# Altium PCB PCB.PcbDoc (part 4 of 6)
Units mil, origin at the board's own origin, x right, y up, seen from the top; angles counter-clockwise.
Board outline 7100 x 7000 mil, 4 copper layers (Top Layer, GND, VCC, Bottom Layer), stack 61.2 mil thick; 759 components, 507 nets, 2200 pads, 452 vias.
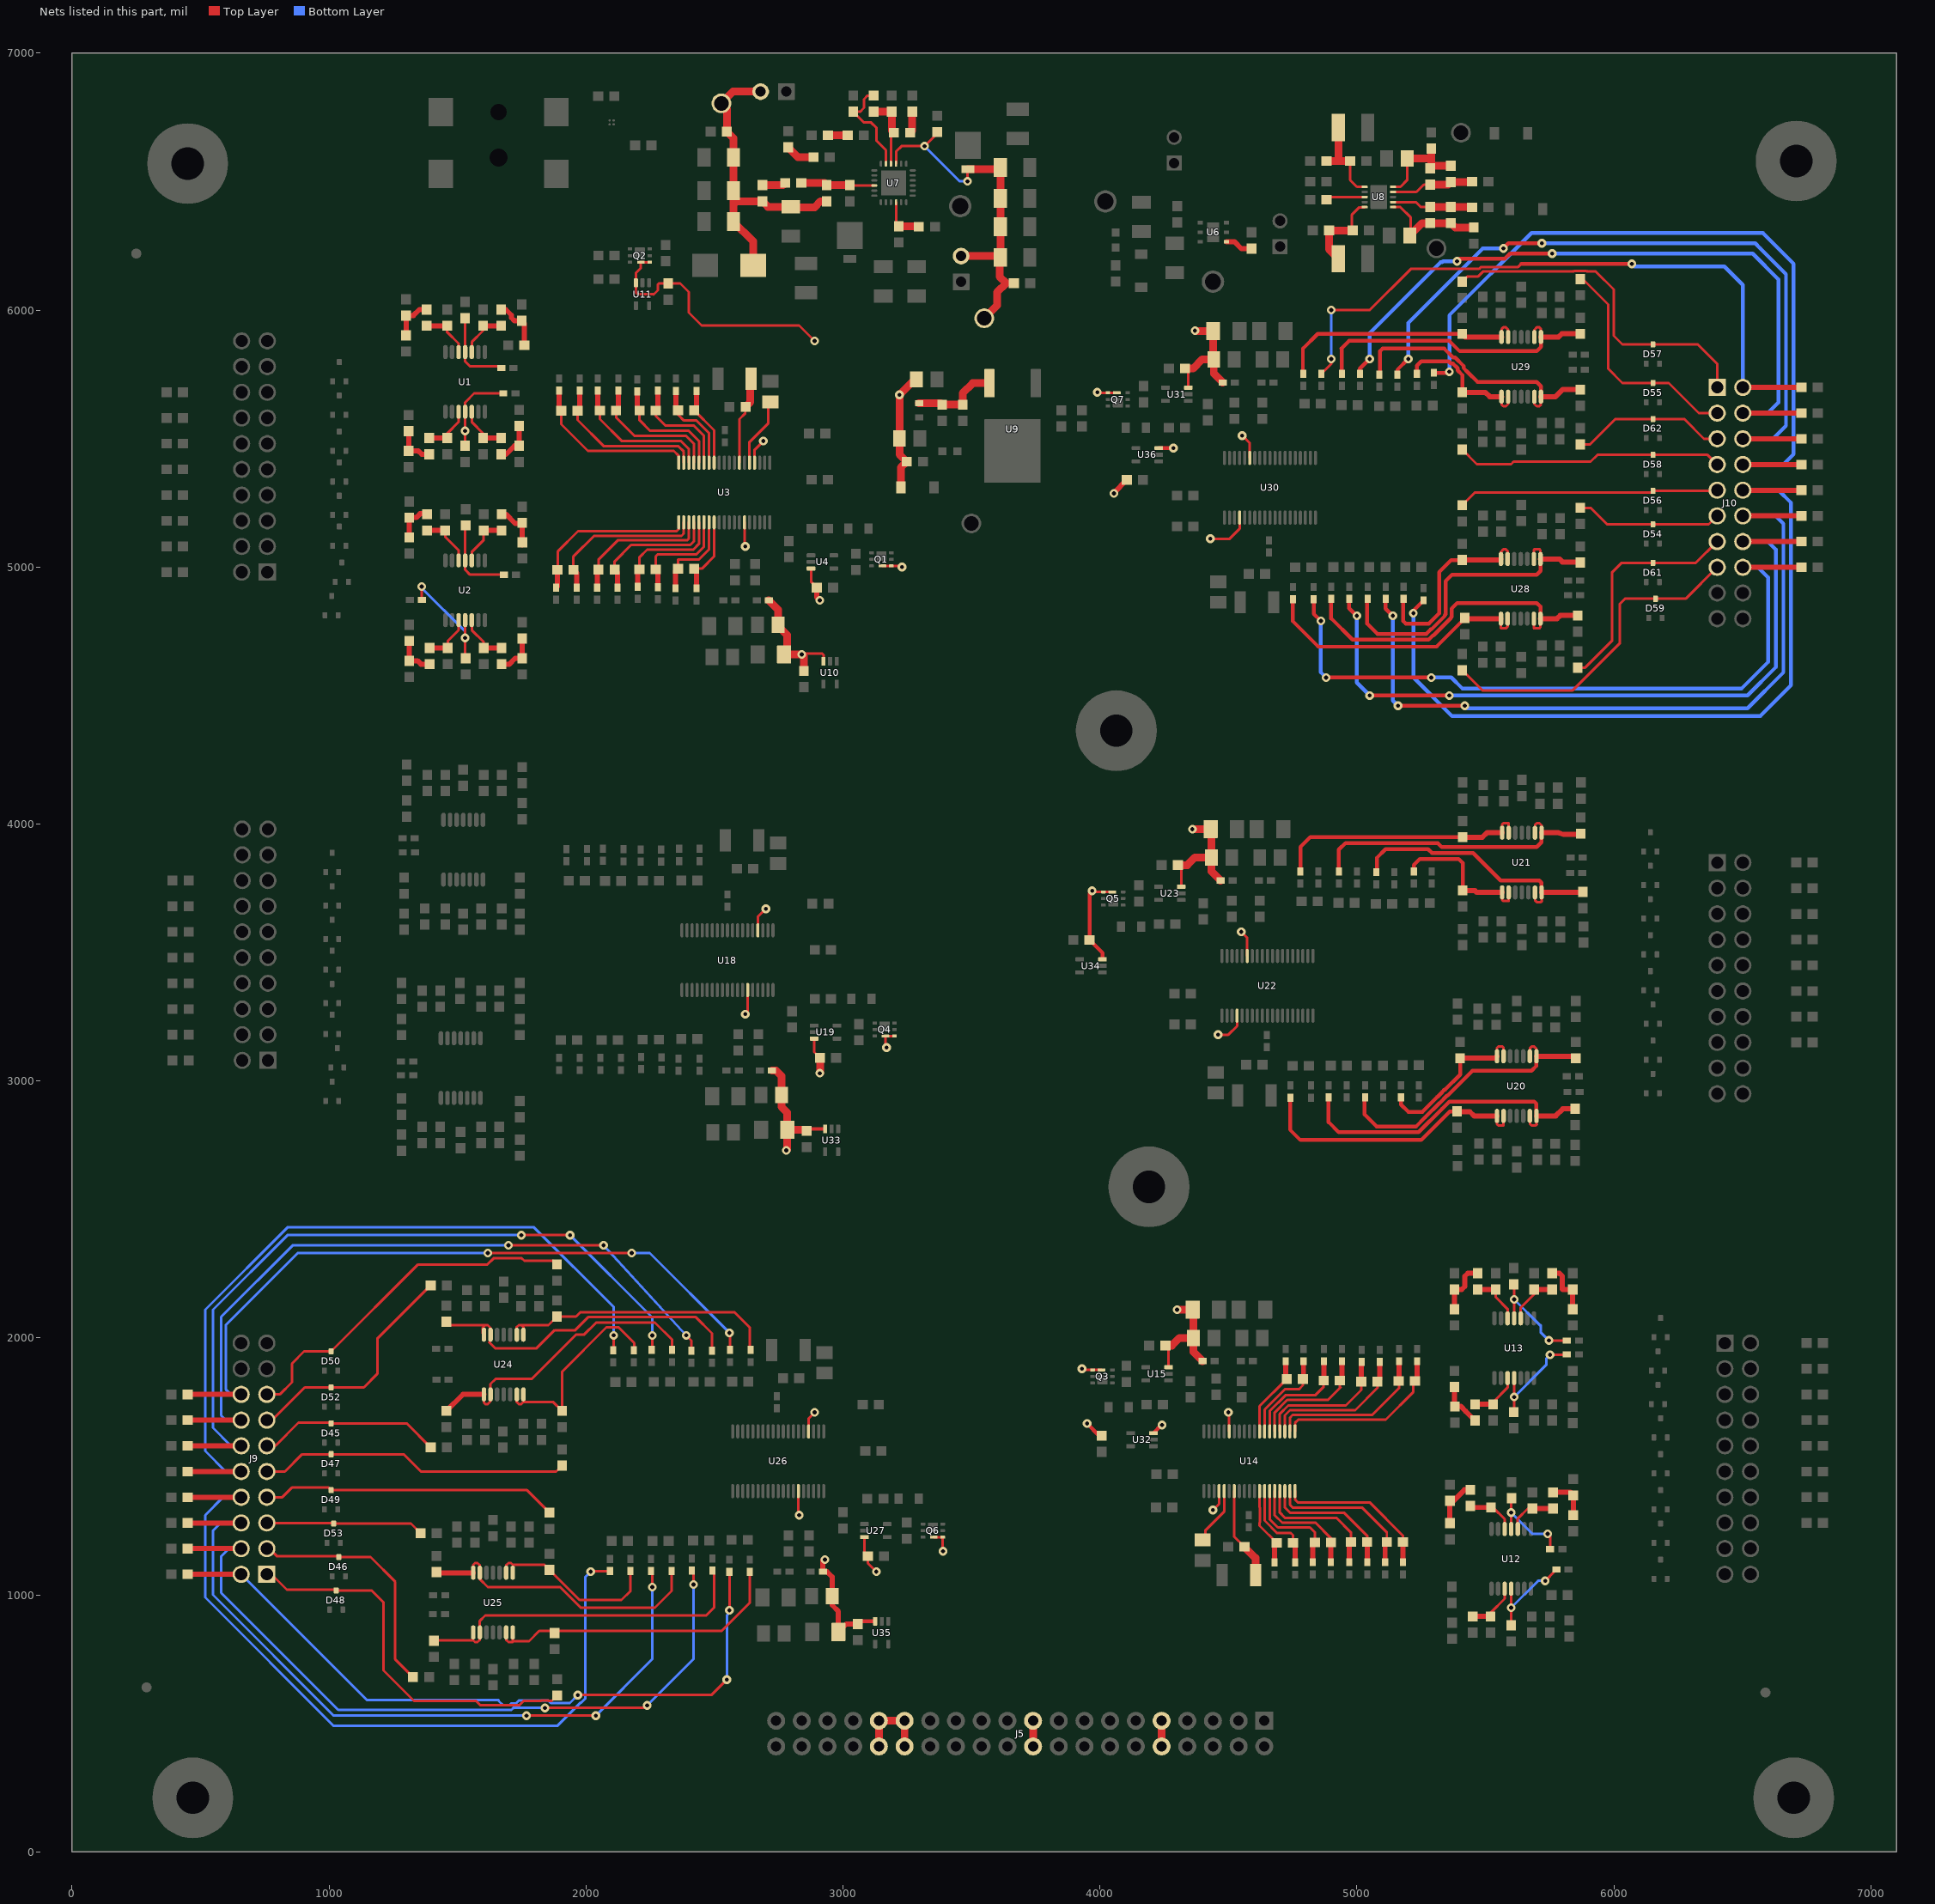
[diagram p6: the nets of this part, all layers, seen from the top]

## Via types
v1: diameter 34, hole 16, Top Layer to Bottom Layer, 440 vias
v2: diameter 19.68, hole 7.87, Top Layer to Bottom Layer, 11 vias
v3: diameter 30, hole 14, Top Layer to Bottom Layer, 1 vias

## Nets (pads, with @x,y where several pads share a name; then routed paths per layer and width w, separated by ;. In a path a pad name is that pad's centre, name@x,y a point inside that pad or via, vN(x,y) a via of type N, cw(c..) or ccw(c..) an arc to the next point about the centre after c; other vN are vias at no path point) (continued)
DGND: C8.2 C9.2 C10.2 C34.2 C70.2 C71.2 C75.2 C83.2 C84.2 C85.2 C109.2 C121.2 C122.2 C123.2 C147.2 C159.2 C160.2 C161.2 C185.2 C197.2 C198.2 C199.2 C223.2 C235.2 C236.2 C237.2 C261.2 C266.2 C267.2 C268.2 C269.2 C270.2 C271.2 D16.2 J5.9 J5.10 J5.19 J5.20 J5.29 J5.30 J5.31 J5.32 Q1.4 Q1.7 Q2.4 Q2.7 Q3.4 Q3.7 Q4.4 Q4.7 Q5.4 Q5.7 Q6.4 Q6.7 Q7.4 Q7.7 R70.2 U3.4 U3.33 U4.3 U10.3 U11.3 U14.4 U14.33 U15.3 U18.4 U18.33 U19.3 U22.4 U22.33 U23.3 U26.4 U26.33 U27.3 U30.4 U30.33 U31.3 U32.3 U33.3 U34.3 U35.3 U36.3 | length 7678
  Top Layer w10: Q2.4@2248.39,6186.38 Q2.7@2213.74,6186.38 2213.74,6164.06 2194.41,6144.72 U11.3@2194.41,6106.26 2194.41,6067.87 2200.32,6061.97 2261.65,6061.97 2263.31,6060.31 2280,6077.01 2280,6100.31 2283.15,6103.46 C75.2@2320,6103.46 2366.54,6103.46 2400,6070 2400,5990 2450,5940 2830,5940 v1(2890,5880) ; U3.33@2617,5173.86 2617,5083 2618.81,5081.19 2618.81,5075.91 v1@2620,5074.72 ; v1(2620,3260) 2629.36,3269.36 U18.33@2629.36,3353.8 ; v1(2620,5080) v1@2620,5074.72 ; v1@2624.04,5070.68 v1@2620,5074.72 ; U3.4@2656.37,5406.14 2656.37,5456.37 v1(2690,5490) ; U18.4@2668.73,3586.09 2668.73,3638.73 v1(2700,3670) ; U26.33@2827,1403.81 2827,1313 v1(2830,1310) ; v1(2840,4660) 2843,4663 2920,4663 2924.41,4658.59 U10.3@2924.41,4633.29 ; U26.4@2866.37,1636.09 2866.37,1686.37 v1(2890,1710) ; U4.3@2875.71,4994.41 2875.71,4942.79 C34.2@2898.5,4920 ; U19.3@2888.07,3164.41 2888.07,3112.8 C147.2@2910.87,3090 ; U27.3@3083.96,1224.41 3083.96,1162.8 C223.2@3096.76,1150 3096.76,1123.24 v1(3130,1090) ; Q1.7@3153.74,5004.41 Q1.4@3188.39,5004.41 3225.59,5004.41 v1(3230,5000) ; v1(3170,3130) 3166.1,3133.9 Q4.7@3166.1,3174.41 Q4.4@3200.75,3174.41 ; Q6.7@3353.74,1224.41 Q6.4@3388.39,1224.41 3388.39,1181.61 3390,1180 v1(3390,1170) ; v1(3930,1880) 3934.41,1875.59 Q3.4@3971.61,1875.59 Q3.7@4006.26,1875.59 ; v1(3970,3740) 3980,3740 3984.41,3735.59 Q5.4@4013.66,3735.59 Q5.7@4048.3,3735.59 ; v1(3990,5680) 4000,5680 4001.98,5678.02 Q7.4@4031.61,5678.02 Q7.7@4066.25,5678.02 ; C109.2@4254.84,1970 4267.64,1957.2 U15.3@4267.64,1885.59 ; C185.2@4303.54,3840 4316.34,3827.21 U23.3@4316.34,3755.59 ; C261.2@4331.5,5772.44 4344.29,5759.65 U31.3@4344.29,5698.03 ; v1(4430,5110) 4505.28,5110 4541.97,5146.69 4541.97,5147.25 4543.78,5149.06 U30.4@4543.78,5192.44 ; v1(4440,1330) 4463.94,1353.94 U14.4@4463.94,1403.86 ; v1(4460,3180) 4500,3180 4533.94,3213.94 U22.4@4533.94,3254.17 ; v1(4500,1710) 4503.31,1706.69 U14.33@4503.31,1636.14 ; v1(4550,3580) 4573.31,3556.69 U22.33@4573.31,3486.46 ; v1(4553.31,5511.18) 4555.12,5511.18 4583.15,5483.15 U30.33@4583.15,5424.72
  Top Layer w15: C268.2@2859,2805.5 2866.8,2813.29 U33.3@2930.41,2813.29 ; C270.2@3058,886.5 3068.8,897.29 U35.3@3125.41,897.29 ; v1(3950,1667) 3997.5,1619.5 C267.2@4007,1619.5 ; v1(3970,3740) 3959.5,3729.5 C269.2@3959.5,3549 4010.29,3498.2 U34.3@4010.29,3473.59 ; U32.3@4208.29,1629.59 4239.7,1661 v1(4242,1661) ; U36.3@4229.29,5462.59 4285.59,5462.59 v1(4286,5463)
  Top Layer w20: C34.2@2898.5,4920 2898.5,4881.5 v1(2910,4870) ; v1(2930,1137) 2924,1137 2921.88,1134.88 C199.2@2921.88,1089.95 2938.26,1089.95 2958.26,1069.95 C197.2@2958.26,995.38 2958.26,959.95 2982.51,935.7 C198.2@2982.51,855.38 3013.62,886.5 C270.2@3058,886.5 ; v1(4055,5287) 4055,5289.5 C271.2@4104.5,5339
  Top Layer w30: C10.2@2711.88,4870 2748.26,4833.62 C8.2@2748.26,4775.38 2748.26,4769.38 2782.26,4735.38 2782.26,4671.08 C9.2@2771.18,4660 v1(2840,4660) 2848,4652 C266.2@2848,4595.5 ; C123.2@2724.24,3040 2740,3040 2760.62,3019.38 C121.2@2760.62,2945.38 2760.62,2899.38 2783.54,2876.46 C122.2@2783.54,2810 ; v1(2780,2730) 2783.54,2733.54 C122.2@2783.54,2810 ; C268.2@2859,2805.5 2854.5,2810 C122.2@2783.54,2810 ; v1(2910,3030) 2910.87,3030.87 C147.2@2910.87,3090 ; J5.32@3140,410 J5.31@3140,510 J5.29@3240,510 J5.30@3240,410 ; D16.2@3225.53,5310 3225.53,5387.03 C71.2@3248.5,5410 3220,5438.5 C70.2@3220,5500 v1(3220,5670) 3280.39,5730.39 R70.2@3286.18,5730.39 ; J5.20@3740,410 J5.19@3740,510 ; J5.10@4240,410 J5.9@4240,510 ; C109.2@4254.84,1970 4280,1970 4310,2000 C83.2@4363.35,2000 ; C185.2@4303.54,3840 4340,3840 4370,3870 C159.2@4433.35,3870 ; v1@4310,2110 C84.2@4360.87,2110 4363.35,2107.52 C83.2@4363.35,2000 ; C261.2@4331.5,5772.44 4362.44,5772.44 4398.26,5808.26 C235.2@4443.19,5808.26 ; v1(4360,3980) C160.2@4430.87,3980 4433.35,3977.52 C159.2@4433.35,3870 ; v1(4370,5920) 4371.74,5918.26 C236.2@4440.71,5918.26 4440.71,5810.74 C235.2@4443.19,5808.26 ; C85.2@4399.72,1910 4363.35,1946.38 C83.2@4363.35,2000 ; C161.2@4469.72,3780 4433.35,3816.38 C159.2@4433.35,3870 ; C237.2@4478.27,5718.26 4443.19,5753.34 C235.2@4443.19,5808.26
  other v1: 4300,2110
DO0+: C164.1 R175.1 U20.8 U20.9 | length 1137.8
  Top Layer w10: U20.9@5673.23,3096.14 5673.23,3126.77 5680,3133.54 5690,3133.54 5698.82,3124.72 U20.8@5698.82,3096.14
  Top Layer w15: R175.1@5031.81,2936.38 5030,2934.57 5030,2870 5076.7,2823.3 5230.95,2823.3 5264.78,2857.13 5322.4,2914.75 5322.88,2914.75 5351.01,2942.87 5352.87,2942.87 5450,3040 5680,3040 5698.82,3058.82 U20.8@5698.82,3096.14
  Top Layer w20: U20.8@5698.82,3096.14 5844.41,3096.14 C164.1@5852.05,3088.5
DO1+: C173.1 R177.1 U20.13 U20.14 | length 635.7
  Top Layer w10: U20.14@5545.28,3096.14 5545.28,3128.82 5550,3133.54 5566.46,3133.54 5570.87,3129.13 U20.13@5570.87,3096.14
  Top Layer w15: R177.1@5171.81,2936.38 5171.81,2908.19 5200,2880 5255.3,2880 5312.93,2937.63 5313.41,2937.63 5332.37,2956.59 5332.37,2957.07 5341.05,2965.75 5343.4,2965.75 5402.05,3024.4 C173.1@5402.05,3088.5
  Top Layer w20: C173.1@5402.05,3088.5 5537.64,3088.5 U20.14@5545.28,3096.14
DO2+: C183.1 R184.1 U21.1 U21.2 | length 584.9
  Top Layer w10: U21.1@5565.28,3733.86 5565.28,3704.72 5570,3700 5590,3700 5590.87,3700.87 U21.2@5590.87,3733.86
  Top Layer w15: R184.1@5221.95,3815.43 5221.95,3841.02 5245.18,3864.25 5395.75,3864.25 5412.05,3847.95 C183.1@5412.05,3741.5
  Top Layer w20: C183.1@5412.05,3741.5 5413.54,3740 5460,3740 5466.14,3733.86 U21.1@5565.28,3733.86
DO3+: C189.1 R187.1 U21.6 U21.7 | length 1062.3
  Top Layer w10: U21.6@5693.23,3733.86 5693.23,3703.23 5700,3696.46 5716.46,3696.46 5720,3700 5718.82,3701.18 U21.7@5718.82,3733.86
  Top Layer w15: R187.1@5076,3812.63 5077.64,3814.27 5077.64,3867.89 5112.13,3902.37 5277.63,3902.37 5292.87,3887.13 5452.87,3887.13 5560,3780 5710,3780 5718.82,3771.18 U21.7@5718.82,3733.86
  Top Layer w20: U21.7@5718.82,3733.86 C189.1@5882.05,3733.86
DO4+: C165.1 R189.1 U21.8 U21.9 | length 1184.2
  Top Layer w10: U21.9@5693.23,3966.14 5693.23,3996.77 5700,4003.54 5710,4003.54 5718.82,3994.72 U21.8@5718.82,3966.14
  Top Layer w15: R189.1@4930,3815.43 4930,3900 4955.63,3925.63 5071.77,3925.63 5072.16,3925.25 5314.75,3925.25 5330,3910 5700,3910 5718.82,3928.82 U21.8@5718.82,3966.14
  Top Layer w20: U21.8@5718.82,3966.14 5783.86,3966.14 5804.45,3959 C165.1@5875,3959
DO5+: C174.1 R191.1 U21.13 U21.14 | length 1000.2
  Top Layer w10: U21.14@5565.28,3966.14 5565.28,3998.82 5570,4003.54 5590,4003.54 5590.87,4002.68 U21.13@5590.87,3966.14
  Top Layer w15: R191.1@4780,3815.43 4780,3910 4818.5,3948.5 C174.1@5412.05,3948.5
  Top Layer w20: C174.1@5412.05,3948.5 5488.5,3948.5 5506.14,3966.14 U21.14@5565.28,3966.14
DO6+: C184.1 R193.1 U20.1 U20.2 | length 1098.3
  Top Layer w10: U20.1@5545.28,2863.86 5545.28,2831.18 5550,2826.46 5570,2826.46 5570.87,2827.32 U20.2@5570.87,2863.86
  Top Layer w15: R193.1@4741.81,2935.08 4740,2933.27 4740,2810 4780,2770 5250,2770 5361.5,2881.5 C184.1@5390,2881.5
  Top Layer w20: C184.1@5390,2881.5 5391.5,2880 5440,2880 5456.14,2863.86 U20.1@5545.28,2863.86
DO7+: C188.1 R195.1 U20.6 U20.7 | length 1281.1
  Top Layer w10: U20.6@5673.23,2863.86 5673.23,2833.23 5680,2826.46 5696.46,2826.46 5700,2830 5698.82,2831.18 U20.7@5698.82,2863.86
  Top Layer w15: R195.1@4890.02,2936.38 4890,2840 4930,2800 5240,2800 5240.43,2800.43 5331.88,2891.88 5332.36,2891.88 5360.48,2920 5362.35,2920 5690,2920 5698.82,2911.18 U20.7@5698.82,2863.86
  Top Layer w20: U20.7@5698.82,2863.86 5773.86,2863.86 5801.5,2891.5 C188.1@5850,2891.5
E0+: D45.3 J9.11 R208.1 | length 714.1
  Top Layer w10: J9.11@758.26,1579.95 791.48,1579.95 881.48,1669.95 1005.66,1669.95 D45.3@1008.26,1667.35 1302.51,1667.35 R208.1@1395.46,1574.4
E0-: J9.12 R219.2 R221.1 | length 2898.1
  Top Layer w10: v1(1748.26,2399.95) v1(1938.26,2399.95) ; R221.1@2255.76,1953.06 2258.26,1955.56 v1(2258.26,2009.95)
  Top Layer w20: R219.2@449.75,1579.95 J9.12@658.26,1579.95
  Bottom Layer w10: J9.12@658.26,1579.95 618.26,1579.95 548.26,1649.95 548.26,2109.95 838.26,2399.95 v1(1748.26,2399.95) ; v1(1938.26,2399.95) 2258.26,2079.95 v1(2258.26,2009.95)
E1+: D47.3 J9.9 R225.1 | length 1213.9
  Top Layer w10: J9.9@758.26,1479.95 828.26,1479.95 895.66,1547.36 D47.3@1008.25,1547.36 1290.85,1547.36 1358.08,1480.13 1884.18,1480.13 R225.1@1906.96,1502.9
E1-: J9.10 R218.2 R224.1 | length 2951.9
  Top Layer w10: R224.1@2105.78,1951.74 2108.26,1954.22 v1(2108.26,2010)
  Top Layer w20: R218.2@449.75,1479.95 J9.10@658.26,1479.95
  Bottom Layer w10: J9.10@658.26,1479.95 598.26,1479.95 518.26,1559.95 518.26,2109.95 838.31,2430 1798.21,2430 2108.26,2119.95 v1(2108.26,2010)
E2+: D49.3 J9.7 R242.1 | length 1155.9
  Top Layer w10: J9.7@758.26,1379.95 818.26,1379.95 855.66,1417.35 998.26,1417.35 D49.3@1008.25,1407.36 1770.69,1407.36 R242.1@1858.26,1319.79
E2-: J9.8 R217.2 R231.1 | length 3006
  Top Layer w10: v1(2018.26,1089.95) 2020.65,1092.34 R231.1@2093.5,1092.34
  Top Layer w20: R217.2@449.75,1379.95 J9.8@658.26,1379.95
  Bottom Layer w10: J9.8@658.26,1379.95 588.26,1379.95 518.26,1309.95 518.26,989.95 1018.26,489.95 1888.26,489.95 1978.38,580.08 1980.63,580.08 1998.13,597.58 1998.13,599.82 1998.26,599.95 1998.26,1069.95 v1(2018.26,1089.95)
E3+: D53.3 J9.5 R251.1 | length 625.5
  Top Layer w10: J9.5@765.66,1287.35 J9.5@758.26,1279.95 1015.66,1279.95 D53.3@1018.25,1277.36 1319.35,1277.36 R251.1@1356.76,1239.95
E3-: J9.6 R216.2 R233.1 | length 2921.1
  Top Layer w10: v1(1768.26,529.95) v1(2038.26,529.95) ; R233.1@2253.52,1092.34 2258.26,1087.61 v1(2258.26,1029.95)
  Top Layer w20: R216.2@449.75,1279.95 J9.6@658.26,1279.95
  Bottom Layer w10: J9.6@658.26,1279.95 578.26,1279.95 548.26,1249.95 548.26,999.95 1018.26,529.95 v1(1768.26,529.95) ; v1(2038.26,529.95) 2258.26,749.95 v1(2258.26,1029.95)
E4+: D46.3 J9.3 R210.1 | length 952.7
  Top Layer w10: J9.3@758.26,1179.95 768.26,1179.95 798.26,1149.95 1035.66,1149.95 D46.3@1038.25,1147.36 1161.64,1147.36 1258,1051 1258,748.71 R210.1@1326.76,679.95
E4-: J9.4 R215.2 R235.1 | length 2902.1
  Top Layer w10: v1(1840,559.95) 2238.26,559.95 v1(2238.26,569.95) ; R235.1@2411.73,1093.98 2418.26,1087.45 v1(2418.26,1039.95)
  Top Layer w20: R215.2@449.75,1179.95 J9.4@658.26,1179.95
  Bottom Layer w10: J9.4@658.26,1179.95 610.3,1179.95 580.3,1149.95 580.3,1007.9 1035.95,552.25 1709.78,552.25 1717.48,559.95 v1(1840,559.95) ; v1(2238.26,569.95) 2418.26,749.95 v1(2418.26,1039.95)
E5+: D48.3 J9.1 R227.1 | length 1514
  Top Layer w10: J9.1@758.26,1079.95 776.21,1079.95 836.21,1019.95 1025.66,1019.95 D48.3@1028.25,1017.36 1165.64,1017.36 1212,971 1212,706.21 1330.58,587.63 1572.37,587.63 1589.87,570.13 1740.13,570.13 1757.63,587.63 1825.43,587.63 1827.63,589.82 1852.37,589.82 1854.57,587.63 1867.43,587.63 R227.1@1888.26,608.45
E5-: J9.2 R214.2 R237.1 | length 2800.4
  Top Layer w10: v1(1968.26,609.95) 2488.26,609.95 v1(2548.26,669.95) ; v1(2558.26,939.95) R237.1@2558.26,1089.95
  Top Layer w20: R214.2@449.75,1079.95 J9.2@658.26,1079.95
  Bottom Layer w10: J9.2@658.26,1079.95 1148.21,590 1660.13,590 1660.13,587.63 1677.63,570.13 1702.37,570.13 1710.07,577.82 1728.88,577.82 1728.88,578.88 1739.82,589.82 1852.37,589.82 1863.32,578.88 1937.18,578.88 v1(1968.26,609.95) ; v1(2548.26,669.95) 2548.26,919.95 2568.26,939.95 v1(2558.26,939.95)
E6+: D50.3 J9.15 R244.1 | length 1400.5
  Top Layer w10: J9.15@758.26,1779.95 808.26,1779.95 855.89,1827.59 855.89,1899.95 903.3,1947.36 D50.3@1008.25,1947.36 1346.79,2285.9 1616.45,2285.9 1640.43,2309.87 1750.13,2309.87 1760.13,2299.87 1872.98,2299.87 R244.1@1886.96,2285.9
E6-: J9.16 R213.2 R239.1 | length 2798.9
  Top Layer w10: v1(1618.26,2329.95) v1(2178.26,2329.95) ; v1(2558.26,2019.95) 2560.21,2018 R239.1@2560.21,1953.06
  Top Layer w20: R213.2@449.75,1779.95 J9.16@658.26,1779.95
  Bottom Layer w10: J9.16@658.26,1779.95 618.26,1779.95 598.26,1799.95 598.26,2049.95 878.26,2329.95 v1(1618.26,2329.95) ; v1(2178.26,2329.95) 2248.26,2329.95 v1(2558.26,2019.95)
E7+: D52.3 J9.13 R247.1 | length 934.8
  Top Layer w10: J9.13@758.26,1679.95 778.26,1679.95 905.66,1807.35 D52.3@1008.26,1807.35 1135.66,1807.35 1188.26,1859.95 1188.26,1997.19 R247.1@1395.46,2204.4
E7-: J9.14 R212.2 R241.1 | length 2824
  Top Layer w10: v1(1698.26,2359.95) v1(2068.26,2359.95) ; v1(2390,2010) 2410.21,1989.79 R241.1@2410.21,1950.78
  Top Layer w20: R212.2@449.75,1679.95 J9.14@658.26,1679.95
  Bottom Layer w10: J9.14@658.26,1679.95 598.26,1679.95 580.3,1697.9 580.3,2082 858.26,2359.95 v1(1698.26,2359.95) ; v1(2068.26,2359.95) v1(2390,2010)
EO0+: C202.1 R220.1 U24.8 U24.9 | length 1177.8
  Top Layer w10: U24.8@1602.99,1780.29 1602.99,1748.16 1608.26,1742.89 1618.26,1742.89 1628.58,1753.21 U24.9@1628.58,1780.29 1628.58,1820.27 1648.26,1839.95 1788.26,1839.95 1960.38,2012.08 1992.08,2012.08 2040,2060 2268.21,2060 2335.76,1992.45 R220.1@2335.76,1953.06
  Top Layer w20: C202.1@1456.96,1715.9 1521.35,1780.29 U24.8@1602.99,1780.29
EO1+: C211.1 R222.1 U24.13 U24.14 | length 787
  Top Layer w10: U24.13@1730.94,1780.29 1730.94,1750.21 1738.26,1742.89 1748.26,1742.89 1756.53,1751.16 1871.69,1751.16 C211.1@1906.96,1715.9 1906.96,1868.65 2079.18,2040.87 2127.34,2040.87 2188.26,1979.95 2188.26,1954.22 R222.1@2185.78,1951.74
EO2+: C221.1 R229.1 U25.1 U25.2 | length 667.5
  Top Layer w10: U25.2@1689.44,1086.09 1689.44,1114.68 1698.26,1123.49 1708.26,1123.49 1715.03,1116.72 1838.34,1116.72 C221.1@1858.26,1096.8 1975.11,979.95 2138.26,979.95 2173.5,1015.19 R229.1@2173.5,1092.34
EO3+: C227.1 R232.1 U25.6 U25.7 | length 1156.9
  Top Layer w10: U25.7@1561.48,1086.09 1561.48,1116.72 1568.26,1123.49 1578.26,1123.49 1587.08,1114.68 U25.6@1587.08,1086.09 1587.08,1061.39 1618.51,1029.95 1899.83,1029.95 1979.83,949.95 2268.26,949.95 2333.52,1015.21 R232.1@2333.52,1092.34
  Top Layer w20: C227.1@1418.26,1088.45 1420.62,1086.09 U25.7@1561.48,1086.09
EO4+: C203.1 R234.1 U25.8 U25.9 | length 1338.6
  Top Layer w10: C203.1@1408.26,821.45 1409.99,823.18 1561.48,823.18 1568.26,816.41 1578.26,816.41 1587.08,825.23 U25.9@1587.08,853.81 1587.08,898.77 1608.26,919.95 2468.26,919.95 2498.26,949.95 2498.26,1087.45 R234.1@2491.73,1093.98
EO5+: C212.1 R236.1 U25.13 U25.14 | length 1206.9
  Top Layer w10: U25.13@1689.44,853.81 1689.44,825.23 1698.26,816.41 1714.71,816.41 1718.26,819.95 ; U25.14@1715.03,853.81 1715.03,823.18 1718.26,819.95 ; R236.1@2638.26,1089.95 2638.26,969.95 2528.26,859.95 1886.76,859.95 C212.1@1878.26,851.45 1869.75,859.95 1818.26,859.95 1778.26,819.95 1718.26,819.95
EO6+: C222.1 R238.1 U24.1 U24.2 | length 1114.5
  Top Layer w10: U24.2@1730.94,2012.57 1730.94,2042.63 1738.26,2049.95 1748.26,2049.95 ; U24.1@1756.53,2012.57 1756.53,2041.68 1748.26,2049.95 ; R238.1@2640.21,1953.06 2638.26,1955.01 2638.26,2039.95 2578.26,2099.95 1978.26,2099.95 1961.21,2082.9 C222.1@1886.96,2082.9 1854,2049.95 1748.26,2049.95
EO7+: C226.1 R240.1 U24.6 U24.7 | length 1303.7
  Top Layer w10: C226.1@1456.96,2062.9 1469.91,2049.95 1608.26,2049.95 ; U24.7@1602.99,2012.57 1598.26,2017.3 1598.26,2039.95 1608.26,2049.95 ; R240.1@2490.21,1950.78 2490.21,2018 2426.13,2082.08 2010.38,2082.08 1958.26,2029.95 1878.26,2029.95 1808.26,1959.95 1646.85,1959.95 1623.75,1983.05 1628.58,1987.87 U24.6@1628.58,2012.57 1628.58,2039.63 1618.26,2049.95 1608.26,2049.95
F0+: D54.3 J10.11 R253.1 | length 572.4
  Top Layer w10: R253.1@5869.69,5230.47 5909.53,5230.47 5973.62,5166.38 D54.3@6152.05,5166.38 6369.45,5166.38 J10.11@6402.05,5198.98
F0-: J10.12 R264.2 R266.1 | length 2976.3
  Top Layer w15: R266.1@5111.79,4876.38 5111.79,4838.21 v1(5140,4810) ; v1(5160,4460) v1(5420,4460)
  Top Layer w20: J10.12@6502.05,5198.98 R264.2@6730.55,5198.98
  Bottom Layer w15: v1(5140,4810) 5140,4480 v1(5160,4460) ; v1(5420,4460) 5430,4450 6520,4450 6660,4590 6660,5168.98 6630,5198.98 J10.12@6502.05,5198.98
F1+: D56.3 J10.9 R270.1 | length 1016.6
  Top Layer w10: R270.1@5409.69,5240.47 5459.21,5290 6145.67,5290 D56.3@6152.05,5296.38 6399.45,5296.38 J10.9@6402.05,5298.98
F1-: J10.10 R263.2 R269.1 | length 3045.7
  Top Layer w15: v1(5220,4820) 5220,4830.66 R269.1@5259.9,4870.56
  Top Layer w20: J10.10@6502.05,5298.98 R263.2@6730.55,5298.98
  Bottom Layer w15: v1(5220,4820) 5220,4570 5370,4420 6570,4420 6690,4540 6690,5250 6641.02,5298.98 J10.10@6502.05,5298.98
F2+: D58.3 J10.7 R287.1 | length 1046.6
  Top Layer w10: R287.1@5409.69,5457.48 5467.04,5400.13 5600.13,5400.13 5610,5410 5910,5410 5936.38,5436.38 D58.3@6152.05,5436.38 6364.65,5436.38 J10.7@6402.05,5398.98
F2-: J10.8 R262.2 R276.1 | length 2988
  Top Layer w15: R276.1@5299.92,5756.06 5356.06,5756.06 v1(5360,5760)
  Top Layer w20: J10.8@6502.05,5398.98 R262.2@6730.55,5398.98
  Bottom Layer w15: v1(5360,5760) 5360,5980 5680,6300 6580,6300 6700,6180 6700,5438.98 6660,5398.98 J10.8@6502.05,5398.98
F3+: D62.3 J10.5 R296.1 | length 605.4
  Top Layer w10: R296.1@5869.69,5477.48 5907.48,5477.48 6006.38,5576.38 D62.3@6152.05,5576.38 6273.62,5576.38 6351.02,5498.98 J10.5@6402.05,5498.98
F3-: J10.6 R261.2 R278.1 | length 2874.1
  Top Layer w15: R278.1@5157.81,5749.08 5157.81,5767.81 v1(5200,5810) ; v1(5570,6240) 5590,6260 v1(5720,6260)
  Top Layer w20: J10.6@6502.05,5498.98 R261.2@6730.55,5498.98
  Bottom Layer w15: v1(5200,5810) 5200,5950 5490,6240 v1(5570,6240) ; v1(5720,6260) 6550,6260 6570,6240 6670,6140 6670,5550 6618.98,5498.98 J10.6@6502.05,5498.98
F4+: D55.3 J10.3 R255.1 | length 894.8
  Top Layer w10: R255.1@5869.69,6120.47 5879.53,6120.47 5978,6022 5978,5772 6033.62,5716.38 D55.3@6152.05,5716.38 6213.62,5716.38 6331.02,5598.98 J10.3@6402.05,5598.98
F4-: J10.4 R260.2 R280.1 | length 2797.2
  Top Layer w15: R280.1@5011.81,5751.89 5011.81,5771.81 v1(5050,5810) ; v1(5390,6190) 5399.63,6199.63 5575.41,6199.63 5595.78,6220 v1(5760,6220)
  Top Layer w20: J10.4@6502.05,5598.98 R260.2@6730.55,5598.98
  Bottom Layer w15: v1(5050,5810) 5050,5910 5326.24,6186.24 5332.27,6186.24 5336.03,6190 v1(5390,6190) ; v1(5760,6220) 6540,6220 6640,6120 6640,5640 6598.98,5598.98 J10.4@6502.05,5598.98
F5+: D57.3 J10.1 R272.1 | length 1357.4
  Top Layer w10: R272.1@5409.69,6110.47 5429.21,6130 5470.9,6130 5490.9,6150 5842.62,6150 5845.65,6153.03 5893.72,6153.03 5896.75,6150 5930,6150 6000,6080 6000,5900 6033.62,5866.38 D57.3@6152.05,5866.38 6326.61,5866.38 6402.05,5790.94 J10.1@6402.05,5698.98
F5-: J10.2 R259.2 R282.1 | length 2602
  Top Layer w10: R282.1@4861.81,5751.89 4861.89,5751.89 4900,5790 v1(4900,5810) ; v1(4900,6000) 5050,6000 5210,6160 5475.62,6160 5483.5,6167.87 5627.87,6167.87 5640,6180
  Top Layer w15: 5640,6180 v1(6070,6180)
  Top Layer w20: J10.2@6502.05,5698.98 R259.2@6730.55,5698.98
  Bottom Layer w10: v1(4900,5810) 4900,5990 v1(4900,6000)
  Bottom Layer w15: v1(6070,6180) 6080,6170 6430,6170 6502.05,6097.95 J10.2@6502.05,5698.98
F6+: D59.3 J10.15 R289.1 | length 1312.6
  Top Layer w10: R289.1@5410,4598.5 5488.5,4520 5840,4520 6024,4704 6024,4857 6043.38,4876.38 D59.3@6162.05,4876.38 6279.45,4876.38 J10.15@6402.05,4998.98
F6-: J10.16 R258.2 R284.1 | length 2777.6
  Top Layer w15: R284.1@4831.79,4875.08 4831.79,4818.21 v1(4860,4790) ; v1(4880,4570) v1(5290,4570)
  Top Layer w20: J10.16@6502.05,4998.98 R258.2@6730.55,4998.98
  Bottom Layer w15: v1(4860,4790) 4860,4590 v1(4880,4570) ; v1(5290,4570) 5367.63,4570 5410,4527.63 6497.63,4527.63 6600,4630 6600,4960 6561.02,4998.98 J10.16@6502.05,4998.98
F7+: D61.3 J10.13 R292.1 | length 901
  Top Layer w10: R292.1@5860,4608.5 5888.5,4608.5 5994,4714 5994,4980 6030.38,5016.38 D61.3@6152.05,5016.38 6319.45,5016.38 J10.13@6402.05,5098.98
F7-: J10.14 R257.2 R286.1 | length 2862.9
  Top Layer w15: R286.1@4970,4876.38 4970,4840 v1(5000,4810) ; v1(5050,4500) v1(5360,4500)
  Top Layer w20: J10.14@6502.05,5098.98 R257.2@6730.55,5098.98
  Bottom Layer w15: v1(5000,4810) 5000,4550 v1(5050,4500) ; v1(5360,4500) 6520,4500 6630,4610 6630,5068.98 6600,5098.98 J10.14@6502.05,5098.98
FO0+: C240.1 R265.1 U28.8 U28.9 | length 1273.7
  Top Layer w10: U28.9@5688.87,5031.12 5688.87,5067.39 5691.48,5070 5710,5070 5714.46,5065.54 U28.8@5714.46,5031.12
  Top Layer w15: R265.1@5041.79,4876.38 5040,4874.59 5040,4780 5080,4740 5270,4740 5287.13,4757.13 5289.47,4757.13 5342.87,4810.53 5342.87,4812.87 5345.37,4815.37 5345.37,4945.37 5370,4970 5700,4970 5714.46,4984.46 U28.8@5714.46,5031.12
  Top Layer w20: U28.8@5714.46,5031.12 5788.88,5031.12 5800,5020 5867.17,5020 C240.1@5869.69,5017.48
FO1+: C248.1 R267.1 U28.13 U28.14 | length 761.2
  Top Layer w10: U28.14@5560.91,5031.12 5560.91,5059.43 5570,5068.52 5580,5068.52 5586.5,5062.02 U28.13@5586.5,5031.12
  Top Layer w15: R267.1@5181.79,4876.38 5180,4874.59 5180,4790 5190,4780 5280,4780 5320,4820 5320,4980 5367.48,5027.48 C248.1@5409.69,5027.48
  Top Layer w20: C248.1@5409.69,5027.48 5557.28,5027.48 U28.14@5560.91,5031.12
FO2+: C259.1 R274.1 U29.1 U29.2 | length 560.4
  Top Layer w10: U29.1@5562.91,5662.83 5562.91,5632.52 5570,5625.43 5580,5625.43 5588.5,5633.94 U29.2@5588.5,5662.83
  Top Layer w15: R274.1@5233.76,5751.89 5233.76,5783.76 5250,5800 5357.65,5800 5365.28,5792.37 5373.41,5792.37 5392.37,5773.41 5392.37,5765.28 5410,5747.65 5410,5680.79 C259.1@5409.69,5680.47
  Top Layer w20: C259.1@5409.69,5680.47 5410.16,5680 5500,5680 5517.17,5662.83 U29.1@5562.91,5662.83
FO3+: C265.1 R277.1 U29.6 U29.7 | length 1084.5
  Top Layer w10: U29.6@5690.87,5662.83 5690.87,5634.57 5700,5625.43 5710,5625.43 5716.46,5631.89 U29.7@5716.46,5662.83
  Top Layer w15: R277.1@5087.81,5749.09 5090,5751.27 5090,5840 5100,5850 5340,5850 5367.13,5822.87 5374.75,5815.25 5382.88,5815.25 5415.25,5782.88 5415.25,5774.75 5432.87,5757.13 5470,5720 5700,5720 5716.46,5703.54 U29.7@5716.46,5662.83
  Top Layer w20: U29.7@5716.46,5662.83 5772.83,5662.83 5800.47,5690.47 C265.1@5869.69,5690.47
FO4+: C241.1 R279.1 U29.8 U29.9 | length 1199.4
  Top Layer w10: U29.9@5690.87,5895.12 5690.87,5923.39 5700,5932.52 5710,5932.52 5716.46,5926.06 U29.8@5716.46,5895.12
  Top Layer w15: R279.1@4941.81,5751.89 4941.81,5848.19 4940,5850 4970,5880 5360,5880 5400,5840 5700,5840 5716.46,5856.46 U29.8@5716.46,5895.12
  Top Layer w20: U29.8@5716.46,5895.12 5785.12,5895.12 5797.48,5907.48 C241.1@5869.69,5907.48
FO5+: C250.1 R281.1 U29.13 U29.14 | length 992
  Top Layer w10: U29.14@5562.91,5895.12 5562.91,5925.43 5570,5932.52 5580,5932.52 5588.5,5924.02 U29.13@5588.5,5895.12
  Top Layer w15: R281.1@4791.81,5751.88 4790,5753.7 4790,5850 4847.48,5907.48 C250.1@5409.69,5907.48
  Top Layer w20: C250.1@5409.69,5907.48 5422.05,5895.12 U29.14@5562.91,5895.12
FO6+: C260.1 R283.1 U28.1 U28.2 | length 1086.3
  Top Layer w10: U28.1@5560.91,4798.83 5560,4797.92 5560,4761.43 5580,4761.43 5586.5,4767.94 U28.2@5586.5,4798.83
  Top Layer w15: R283.1@4751.79,4875.08 4750,4873.29 4750,4790 4850,4690 5310,4690 5410,4790 C260.1@5410,4801.5
  Top Layer w20: C260.1@5412.66,4798.83 U28.1@5560.91,4798.83
FO7+: C264.1 R285.1 U28.6 U28.7 | length 1305.3
  Top Layer w10: U28.6@5688.87,4798.83 5688.87,4762.57 5690,4761.43 5710,4761.43 5714.46,4765.89 U28.7@5714.46,4798.83
  Top Layer w15: R285.1@4900,4876.38 4900,4800 4982.87,4717.13 5279.47,4717.13 5296.6,4734.25 5298.95,4734.25 5365.75,4801.05 5365.75,4803.4 5368.25,4805.9 5368.25,4838.25 5390,4860 5700,4860 5714.46,4845.54 U28.7@5714.46,4798.83
  Top Layer w20: U28.7@5714.46,4798.83 5778.83,4798.83 5791.5,4811.5 C264.1@5860,4811.5
NetC1_2: C1.2 R69.2 U1.4 | length 319.7
  Top Layer w10: C1.2@1530,5968.82 1530,5902.64 U1.4@1530,5836.46 1530,5800 1548,5782 R69.2@1673.38,5782
NetC2_2: C2.2 R310.2 U2.4 | length 332.3
  Top Layer w10: C2.2@1532,5162.19 1530,5160.19 U2.4@1530,5025.83 1530,4989 1549,4970 R310.2@1680.38,4970
NetC3_2: C3.2 R2.2 U1.10 | length 190.8
  Top Layer w10: C3.2@1460,5501.81 1460,5520 1504.41,5564.41 U1.10@1504.41,5604.17
  Top Layer w20: R2.2@1390,5501.81 C3.2@1460,5501.81
NetC4_2: C4.2 R4.2 U2.10 | length 195.9
  Top Layer w10: C4.2@1462,4685.18 1462,4712 1504.41,4754.41 U2.10@1504.41,4793.54
  Top Layer w20: R4.2@1392,4685.18 C4.2@1462,4685.18
NetC11_2: C11.2 R311.2 U1.11 | length 332.1
  Top Layer w10: C11.2@1530,5471.81 v1(1530,5530) U1.11@1530,5604.17 1530,5641 1565,5676 R311.2@1678.38,5676
NetC12_2: C12.2 R312.2 U2.11 | length 471.5
  Top Layer w10: v1(1361,4924) 1361,4915.24 1361.62,4914.62 R312.2@1361.62,4872 ; U2.11@1530,4793.54 v1(1530,4724) 1530,4647.18 C12.2@1532,4645.18
  Bottom Layer w10: v1(1361,4924) 1361,4918 1530,4749 v1(1530,4724)
NetC13_2: C13.2 R1.2 R2.1 | length 162.4
  Top Layer w20: C13.2@1310,5528.82 R1.2@1310,5451.81 1348.19,5451.81 1361.18,5438.82 R2.1@1390,5438.82
NetC14_2: C14.2 R3.2 R4.1 | length 162.4
  Top Layer w20: C14.2@1312,4712.19 R3.2@1312,4635.18 1344.82,4635.18 1357.81,4622.19 R4.1@1392,4622.19
NetC15_1: C15.1 R13.2 U3.16 | length 526.4
  Top Layer w10: C15.1@2117.25,5609.44 2117.25,5582.75 2190,5510 2390,5510 2420.15,5479.85 U3.16@2420.15,5406.14
  Top Layer w20: C15.1@2117.25,5609.44 2125.76,5617.94 R13.2@2125.76,5686.38
NetC15_2: C15.2 R14.2 U3.17 | length 561.9
  Top Layer w10: C15.2@2054.26,5609.44 2054.26,5575.74 2140,5490 2370,5490 2400.46,5459.54 U3.17@2400.46,5406.14
  Top Layer w20: R14.2@2045.76,5686.38 2045.76,5617.94 C15.2@2054.26,5609.44
NetC16_1: C16.1 R15.2 U3.18 | length 624.9
  Top Layer w10: C16.1@1967.27,5608.12 1967.27,5572.73 2070,5470 2360,5470 2380.78,5449.22 U3.18@2380.78,5406.14
  Top Layer w20: C16.1@1967.27,5608.12 1975.78,5616.62 R15.2@1975.78,5686.38
NetC16_2: C16.2 R17.2 U3.19 | length 668.4
  Top Layer w10: C16.2@1904.28,5608.12 1904.28,5555.72 2007.87,5452.13 2341.42,5452.13 2361.09,5432.45 U3.19@2361.09,5406.14
  Top Layer w20: R17.2@1895.78,5686.38 1895.78,5616.62 C16.2@1904.28,5608.12
NetC17_2: C17.2 R19.2 U1.12 | length 190.8
  Top Layer w10: U1.12@1555.59,5604.17 1555.59,5564.41 1600,5520 C17.2@1600,5501.81
  Top Layer w20: C17.2@1600,5501.81 R19.2@1670,5501.81
NetC18_2: C18.2 R21.2 U2.12 | length 197.6
  Top Layer w10: U2.12@1555.59,4793.54 1555.59,4754.41 1602,4708 C18.2@1602,4685.18
  Top Layer w20: C18.2@1602,4685.18 R21.2@1672,4685.18
NetC19_1: C19.1 R22.2 U3.21 | length 636.2
  Top Layer w10: C19.1@1951.5,4989.59 1951.5,5041.5 2031.5,5121.5 2371.5,5121.5 2380.78,5130.78 U3.21@2380.78,5173.86
  Top Layer w20: C19.1@1951.5,4989.59 1963.5,4977.58 R22.2@1963.5,4919.59
NetC19_2: C19.2 R24.2 U3.20 | length 676.8
  Top Layer w10: C19.2@1888.5,4989.59 1890,4991.08 1890,5060 1969.37,5139.37 2352.91,5139.37 2361.09,5147.55 U3.20@2361.09,5173.86
  Top Layer w20: R24.2@1883.5,4919.59 1888.5,4924.59 C19.2@1888.5,4989.59
NetC20_1: C20.1 R25.2 U3.23 | length 521.6
  Top Layer w10: C20.1@2111.75,4990 2111.75,5021.75 2175.75,5085.75 2405.75,5085.75 2420.15,5100.15 U3.23@2420.15,5173.86
  Top Layer w20: C20.1@2111.75,4990 2123.52,4978.23 R25.2@2123.52,4919.59
NetC20_2: C20.2 R26.2 U3.22 | length 560.3
  Top Layer w10: C20.2@2048.76,4990 2048.76,5028.76 2123.62,5103.62 2393.62,5103.62 2400.46,5110.46 U3.22@2400.46,5173.86
  Top Layer w20: R26.2@2043.52,4919.59 2043.52,4984.76 C20.2@2048.76,4990
NetC21_1: C21.1 R27.2 U3.25 | length 421.9
  Top Layer w10: C21.1@2271.5,4991.22 2271.5,5041.5 2280,5050 2430,5050 2459.52,5079.52 U3.25@2459.52,5173.86
  Top Layer w20: C21.1@2271.5,4991.22 2280,4982.72 R27.2@2280,4921.22
NetC21_2: C21.2 R28.2 U3.24 | length 454.3
  Top Layer w10: C21.2@2208.5,4991.22 2208.5,5038.5 2237.87,5067.87 2417.87,5067.87 2439.83,5089.83 U3.24@2439.83,5173.86
  Top Layer w20: R28.2@2201.73,4923.62 2201.73,4984.45 C21.2@2208.5,4991.22
NetC22_2: C22.2 R18.2 R19.1 | length 160.7
  Top Layer w20: R19.1@1670,5438.82 1688.82,5438.82 1721.81,5471.81 R18.2@1740,5471.81 C22.2@1740,5548.82
NetC23_2: C23.2 R20.2 R21.1 | length 166.5
  Top Layer w20: R21.1@1672,4622.19 1702.19,4622.19 1725.18,4645.18 R20.2@1752,4645.18 C23.2@1752,4722.19
NetC24_1: C24.1 U3.5 | length 270.9
  Top Layer w10: U3.5@2636.68,5406.14 2636.68,5486.68 2710,5560 2710,5635 C24.1@2718.26,5643.26
NetC25_1: C25.1 C26.1 U3.7 | length 346.1
  Top Layer w10: U3.7@2597.31,5406.14 2597.31,5575.31 2620,5598 2620,5621.76 C26.1@2621.5,5623.26
  Top Layer w30: C26.1@2621.5,5623.26 2640,5641.76 2640,5730.04 C25.1@2643.22,5733.26
NetC27_1: C27.1 R29.2 U3.27 | length 309.5
  Top Layer w10: C27.1@2421.5,4993.57 2451.02,4993.57 2498.89,5041.44 U3.27@2498.89,5173.86
  Top Layer w20: C27.1@2421.5,4993.57 2430,4985.07 R29.2@2430,4917.19
NetC27_2: C27.2 R30.2 U3.26 | length 358.6
  Top Layer w10: C27.2@2358.5,4993.57 2358.5,5030 2440,5030 2479.2,5069.2 U3.26@2479.2,5173.86
  Top Layer w20: R30.2@2348.26,4917.19 2348.26,4983.32 C27.2@2358.5,4993.57
NetC28_1: C28.1 R31.2 U3.12 | length 315.3
  Top Layer w10: C28.1@2421.5,5609.95 2498.89,5532.56 U3.12@2498.89,5406.14
  Top Layer w20: C28.1@2421.5,5609.95 2430,5618.45 R31.2@2430,5685.82
NetC28_2: C28.2 R32.2 U3.13 | length 361.7
  Top Layer w10: C28.2@2358.5,5609.95 2358.5,5592.9 2381.41,5570 2430,5570 2479.2,5520.8 U3.13@2479.2,5406.14
  Top Layer w20: R32.2@2350,5685.82 2350,5618.45 C28.2@2358.5,5609.95
NetC29_1: C29.1 R33.2 U3.14 | length 426
  Top Layer w10: C29.1@2271.7,5609.44 2271.7,5588.3 2310,5550 2420,5550 2459.52,5510.48 U3.14@2459.52,5406.14
  Top Layer w20: C29.1@2271.7,5609.44 2280.21,5617.94 R33.2@2280.21,5686.38
NetC29_2: C29.2 R34.2 U3.15 | length 464.6
  Top Layer w10: C29.2@2208.71,5609.44 2208.71,5571.29 2250,5530 2400,5530 2439.83,5490.17 U3.15@2439.83,5406.14
  Top Layer w20: R34.2@2200,5683.53 2200,5618.15 C29.2@2208.71,5609.44
NetC30_2: C30.2 R36.2 U2.3 | length 205.6
  Top Layer w10: U2.3@1555.59,5025.83 1555.59,5058.82 1602,5105.23 C30.2@1602,5142.19
  Top Layer w20: C30.2@1602,5142.19 R36.2@1672,5142.19
NetC31_2: C31.2 R38.2 U1.3 | length 190.8
  Top Layer w10: U1.3@1555.59,5836.46 1555.59,5875.59 1600,5920 C31.2@1600,5938.82
  Top Layer w20: C31.2@1600,5938.82 R38.2@1670,5938.82
NetC32_2: C32.2 R35.2 R36.1 | length 182.7
  Top Layer w20: R36.1@1672,5205.18 1689.3,5205.18 1724.8,5169.69 1749.5,5169.69 R35.2@1752,5172.19 C32.2@1752,5085.18
NetC33_2: C33.2 R37.2 R38.1 | length 203.8
  Top Layer w20: R38.1@1670,6001.81 1688.19,6001.81 1710,5980 1710,5970 1721.18,5958.82 R37.2@1750,5958.82 1760.5,5948.32 C33.2@1760.5,5863
NetC35_2: C35.2 R41.2 U1.5 | length 200.8
  Top Layer w10: C35.2@1460,5938.82 1460,5913.86 1504.41,5869.45 U1.5@1504.41,5836.46
  Top Layer w20: R41.2@1380,5938.82 C35.2@1460,5938.82
NetC36_2: C36.2 R45.2 U2.5 | length 208.1
  Top Layer w10: C36.2@1452,5142.19 1452,5118 1504.41,5065.59 U2.5@1504.41,5025.83
  Top Layer w20: R45.2@1382,5142.19 C36.2@1452,5142.19
NetC37_2: C37.2 R40.2 R41.1 | length 166.5
  Top Layer w20: C37.2@1300,5901.81 R40.2@1300,5978.82 1328.82,5978.82 1351.81,6001.81 R41.1@1380,6001.81
NetC38_2: C38.2 R44.2 R45.1 | length 154.5
  Top Layer w20: C38.2@1312,5115.18 R44.2@1312,5192.19 1339.3,5192.19 1354.8,5207.69 1379.5,5207.69 R45.1@1382,5205.18
NetC42_1: C42.1 C43.1 C44.1 C45.1 C46.1 J2.2 R46.2 R47.2 R49.2 TP2.1 | length 1242.9
  Top Layer w30: C42.1@2651.93,6172.76 C42.1@2650.43,6174.25 2650.43,6267.84 C45.1@2574.02,6344.25 2574.02,6410 ; J2.2@2680,6850 2572.36,6850 TP2.1@2526.93,6804.57 2548.43,6783.07 C46.1@2548.43,6694.25 2574.02,6668.66 C43.1@2574.02,6594.25 C44.1@2574.02,6464.25 2574.02,6410 ; R49.2@2936.93,6423.07 2913.07,6423.07 2890,6400 2798.58,6400 R46.2@2796.93,6401.65 2708.35,6401.65 R47.2@2686.93,6423.07 2587.09,6423.07 2574.02,6410
NetC48_1: C48.1 U6.1 | length 108.5
  Top Layer w20: U6.1@4492.3,6265.35 4524.65,6265.35 4550.69,6239.31 C48.1@4590,6239.31
NetC49_2: C49.2 R54.1 U7.17 | length 397.7
  Top Layer w10: R54.1@3120,6834.76 3095.76,6834.76 3082,6821 3082,6787 3066.77,6771.77 C49.2@3040,6771.77 3081.77,6730 3110,6730 3130,6710 3130,6660 3167.4,6622.6 U7.17@3167.4,6569.37
NetC50_1: C50.1 R47.1 | length 92
  Top Layer w30: R47.1@2686.93,6486.06 2766.93,6486.06 C50.1@2775.43,6494.57
NetC50_2: C50.2 R49.1 R50.1 U7.22 | length 287.8
  Top Layer w10: R49.1@2928.43,6494.57 R49.1@2936.93,6486.06 ; R50.1@3026.93,6486.06 3028.27,6484.73 U7.22@3122.13,6484.73
  Top Layer w30: C50.2@2838.43,6494.57 R49.1@2928.43,6494.57 ; R49.1@2936.93,6486.06 R50.1@3026.93,6486.06
NetC51_2: C51.2 R51.2 | length 77
  Top Layer w30: C51.2@2941.5,6680 R51.2@3018.5,6680
NetC52_1: C52.1 R55.1 | length 85.3
  Top Layer w30: C52.1@3261.5,6690 3270,6698.5 R55.1@3270,6771.77
NetC52_2: C52.2 R52.1 R54.2 U7.16 | length 280.7
  Top Layer w10: U7.16@3187.09,6569.37 3187.09,6678.58 C52.2@3198.5,6690
  Top Layer w30: R54.2@3120,6771.77 R52.1@3190,6771.77 3190,6698.5 C52.2@3198.5,6690
NetC53_1: C53.1 C54.1 C57.1 C58.1 C59.1 D15.2 J4.2 R53.2 TP4.1 U7.15 | length 1430.5
  Top Layer w10: U7.15@3206.77,6569.37 3206.77,6616.77 3228,6638 v1(3318,6638) 3366.93,6686.93 R53.2@3366.93,6693.07 ; v1(3485,6501) 3485,6546.64 D15.2@3486.93,6548.57
  Top Layer w30: J4.2@3460,6210 3601.65,6210 C54.1@3610,6201.65 ; D15.2@3486.93,6548.57 3606.91,6548.57 C57.1@3612.91,6554.57 C58.1@3612.91,6434.57 C59.1@3612.91,6324.57 C54.1@3612.91,6204.57 C54.1@3610,6201.65 ; TP4.1@3550,5968 3600,6018 3600,6069.14 3635.43,6104.57 3610,6130 C54.1@3610,6201.65
  Bottom Layer w10: v1(3318,6638) 3455,6501 v1(3485,6501)
NetC55_1: C55.1 R56.2 U7.4 | length 177
  Top Layer w10: U7.4@3206.77,6419.77 3206.77,6336.22 C55.1@3216.93,6326.06
  Top Layer w30: C55.1@3216.93,6326.06 3293.94,6326.06 R56.2@3295.43,6324.57
NetC60_1: C60.1 R57.2 | length 114.5
  Top Layer w30: C60.1@2786.93,6633.07 2825.43,6594.57 R57.2@2885.43,6594.57
NetC61_1: C61.1 C64.1 R58.1 R60.2 U8.10 | length 405.1
  Top Layer w10: U8.10@5140.51,6479.37 5141.14,6480 5170,6480 5195.39,6505.39 C64.1@5195.39,6590
  Top Layer w30: C64.1@5195.39,6590 5281.02,6590 5290,6598.98 ; R60.2@5285.39,6551.5 R60.2@5290,6556.1 ; R58.1@5290,6628.5 5290,6598.98 ; C61.1@5365.39,6561.5 5295.39,6561.5 R60.2@5290,6556.1 ; R60.2@5290,6556.1 5290,6598.98
NetC61_2: C61.2 R60.1 R63.2 U8.9 | length 324.7
  Top Layer w10: U8.9@5140.51,6459.69 5231.81,6459.69 5260.63,6488.5 R60.1@5285.39,6488.5
  Top Layer w30: R60.1@5285.39,6488.5 5355.39,6488.5 C61.2@5365.39,6498.5 5447.01,6498.5 R63.2@5448.5,6500
NetC62_2: C62.2 C63.1 R59.2 U8.1 | length 364
  Top Layer w10: C63.1@4973.9,6580 4973.9,6506.1 5000,6480 5029.65,6480 U8.1@5030.28,6479.37
  Top Layer w30: R59.2@4881.5,6580 4927.7,6580 ; C62.2@4928.31,6710 4928.31,6580.61 4927.7,6580 ; C63.1@4973.9,6580 4927.7,6580
NetC65_1: C65.1 C66.1 R62.2 R67.1 U8.6 | length 428.8
  Top Layer w10: U8.6@5140.51,6400.63 5169.37,6400.63 5210,6360 C66.1@5210,6294.61
  Top Layer w30: C66.1@5205.39,6290 5210,6294.61 5253.9,6338.5 R62.2@5285.39,6338.5 C65.1@5365.39,6338.5 5382.4,6321.5 R67.1@5455.39,6321.5
NetC65_2: C65.2 R62.1 R66.2 U8.7 | length 316.4
  Top Layer w10: U8.7@5140.51,6420.31 5229.69,6420.31 5248.5,6401.5 R62.1@5285.39,6401.5
  Top Layer w30: R62.1@5285.39,6401.5 C65.2@5365.39,6401.5 5447.01,6401.5 R66.2@5448.5,6400
NetC67_1: C67.1 U8.3 | length 152.9
  Top Layer w10: C67.1@4891.5,6440 U8.3@5030.28,6440
  Top Layer w12: C67.1@4881.5,6430 C67.1@4891.5,6440
NetC68_2: C68.2 C69.1 R61.2 U8.5 | length 342.2
  Top Layer w10: C69.1@4983.9,6310 4980,6313.9 4980,6370 5010,6400 5029.65,6400 U8.5@5030.28,6400.63
  Top Layer w30: C68.2@4928.31,6200 4891.5,6236.81 R61.2@4891.5,6310 C69.1@4983.9,6310
NetC72_1: C72.1 FB1.1 R64.2 U9.3 | length 336.7
  Top Layer w30: FB1.1@3296.18,5637.95 3380.12,5637.95 R64.2@3386.18,5631.89 C72.1@3466.18,5631.89 3466.18,5676.18 3505.35,5715.35 U9.3@3569.84,5715.35
NetC76_2: C76.2 R314.2 U12.4 | length 383.9
  Top Layer w10: C76.2@5600.73,881.5 v1(5600.73,950) U12.4@5600.73,1023.86 ; v1(5733,1054.62) 5731.38,1053 5773,1094.62 R314.2@5776.38,1098
  Bottom Layer w10: v1(5600.73,950) 5703.73,1053 5705.35,1054.62 v1(5733,1054.62)
NetC77_2: C77.2 R315.2 U13.4 | length 421.4
  Top Layer w10: C77.2@5610,1711.5 5612.05,1713.54 v1(5612.05,1770) U13.4@5612.05,1843.86 ; v1(5752,1934) 5815.38,1934 R315.2@5817.38,1936
  Bottom Layer w10: v1(5612.05,1770) 5737,1894.95 5737,1919 v1(5752,1934)
NetC78_2: C78.2 R74.2 U12.10 | length 193.5
  Top Layer w10: U12.10@5626.32,1256.14 5626.32,1296.32 5665.75,1335.75 C78.2@5683.35,1335.75
  Top Layer w20: C78.2@5683.35,1335.75 R74.2@5763.35,1335.75
NetC79_2: C79.2 R76.2 U13.10 | length 204.1
  Top Layer w10: U13.10@5637.64,2076.14 5637.64,2117.64 5690,2170 C79.2@5690,2188.5
  Top Layer w20: C79.2@5690,2188.5 R76.2@5760,2188.5
NetC86_2: C86.2 R316.2 U12.11 | length 359.7
  Top Layer w10: U12.11@5600.73,1256.14 v1(5600.73,1320) 5600.73,1374.43 C86.2@5602.05,1375.75 ; v1(5743,1237) 5752.38,1227.62 R316.2@5752.38,1178
  Bottom Layer w10: v1(5600.73,1320) 5683.73,1237 v1(5743,1237)
NetC87_2: C87.2 R317.2 U13.11 | length 421
  Top Layer w10: C87.2@5610,2208.5 5612.05,2206.46 v1(5612.05,2150) U13.11@5612.05,2076.14 ; v1(5748,1990) 5816.38,1990 R317.2@5817.38,1989
  Bottom Layer w10: v1(5612.05,2150) 5713.05,2049 5715,2049 5715,2022 5747,1990 v1(5748,1990)
NetC88_2: C88.2 R73.2 R74.1 | length 160.5
  Top Layer w20: R74.1@5763.35,1398.74 5830.55,1398.74 R73.2@5842.05,1387.24 C88.2@5842.05,1310.24
NetC89_2: C89.2 R75.2 R76.1 | length 212.4
  Top Layer w20: R76.1@5760,2251.5 5788.5,2251.5 5800,2240 5800,2190 5801.5,2188.5 R75.2@5840,2188.5 C89.2@5840,2111.5
NetC90_1: C90.1 R85.2 U14.16 | length 511.1
  Top Layer w10: U14.16@4700.16,1403.86 4700.16,1319.84 4720,1300 4920,1300 4976.69,1243.31 C90.1@4976.69,1205.28
  Top Layer w20: R85.2@4970,1127.24 4970,1198.58 C90.1@4976.69,1205.28
NetC90_2: C90.2 R86.2 U14.17 | length 532.5
  Top Layer w10: U14.17@4719.84,1403.86 4719.84,1340.16 4740,1320 4950,1320 5040,1230 5040,1205.59 C90.2@5039.69,1205.28
  Top Layer w20: C90.2@5039.69,1205.28 5040,1204.96 R86.2@5040,1127.24
NetC91_1: C91.1 R87.2 U14.18 | length 593.8
  Top Layer w10: U14.18@4739.53,1403.86 4739.53,1350.47 4750,1340 5020,1340 5116.69,1243.31 C91.1@5116.69,1205.28
  Top Layer w20: R87.2@5110,1127.24 5110,1198.58 C91.1@5116.69,1205.28
NetC91_2: C91.2 R89.2 U14.19 | length 614.9
  Top Layer w10: U14.19@4759.21,1403.86 4759.21,1370.79 4770,1360 5050,1360 5179.69,1230.32 C91.2@5179.69,1205.28
  Top Layer w20: C91.2@5179.69,1205.28 5180,1204.96 R89.2@5180,1127.24
NetC92_2: C92.2 R91.2 U12.12 | length 192.9
  Top Layer w10: C92.2@5522.05,1340.2 5529.8,1340.2 5575.14,1294.86 U12.12@5575.14,1256.14
  Top Layer w20: R91.2@5442.05,1345.75 5447.6,1340.2 C92.2@5522.05,1340.2
NetC93_2: C93.2 R93.2 U13.12 | length 201.6
  Top Layer w10: C93.2@5540,2188.5 5540,2158.98 5586.46,2112.52 U13.12@5586.46,2076.14
  Top Layer w20: R93.2@5470,2188.5 C93.2@5540,2188.5
NetC94_1: C94.1 R94.2 U14.21 | length 631.9
  Top Layer w10: U14.21@4739.53,1636.14 4739.53,1689.53 4750,1700 5060,1700 5164.45,1804.45 5164.45,1831.3 C94.1@5162.96,1832.8
  Top Layer w20: C94.1@5162.96,1832.8 5164.45,1834.3 R94.2@5164.45,1909.18
NetC94_2: C94.2 R96.2 U14.20 | length 669.1
  Top Layer w10: U14.20@4759.21,1636.14 4759.21,1669.21 4772.13,1682.13 5112.13,1682.13 5220,1790 5220,1826.85 C94.2@5225.95,1832.8
  Top Layer w20: C94.2@5225.95,1832.8 5234.45,1841.3 R96.2@5234.45,1909.18
NetC95_1: C95.1 R97.2 U14.23 | length 533.4
  Top Layer w10: U14.23@4700.16,1636.14 4700.16,1704.32 4732.92,1737.08 4957.08,1737.08 5017.01,1797.01 C95.1@5017.01,1830
  Top Layer w20: C95.1@5017.01,1830 5017.01,1904.88 R97.2@5018.5,1906.38
NetC95_2: C95.2 R98.2 U14.22 | length 571.5
  Top Layer w10: U14.22@4719.84,1636.14 4719.84,1698.73 4740,1718.89 4993.59,1718.89 5080,1805.3 C95.2@5080,1830
  Top Layer w20: C95.2@5080,1830 5088.5,1838.5 R98.2@5088.5,1906.38
NetC96_1: C96.1 R99.2 U14.25 | length 428.8
  Top Layer w10: U14.25@4660.79,1636.14 4660.79,1715.51 4721.89,1776.61 4838.02,1776.61 4871.01,1809.6 C96.1@4871.01,1834.3
  Top Layer w20: C96.1@4871.01,1834.3 4872.5,1835.79 R99.2@4872.5,1909.18
NetC96_2: C96.2 R100.2 U14.24 | length 476.7
  Top Layer w10: U14.24@4680.47,1636.14 4680.47,1709.92 4729.29,1758.74 4888.15,1758.74 4936.5,1807.1 4934,1809.6 C96.2@4934,1834.3
  Top Layer w20: C96.2@4934,1834.3 4942.5,1842.8 R100.2@4942.5,1909.18
NetC97_2: C97.2 R90.2 R91.1 | length 184.8
  Top Layer w20: C97.2@5362.05,1278.74 R90.2@5362.05,1365.75 5375.75,1365.75 5418.74,1408.74 R91.1@5442.05,1408.74
NetC98_2: C98.2 R92.2 R93.1 | length 216.5
  Top Layer w20: C98.2@5380,2111.5 R92.2@5380,2188.5 5408.5,2188.5 5420,2200 5420,2240 5431.5,2251.5 R93.1@5470,2251.5
NetC99_1: C99.1 U14.5 | length 210.4
  Top Layer w10: C99.1@4410,1224 4410,1250 4483.62,1323.62 U14.5@4483.62,1403.86
NetC100_1: C100.1 C101.1 U14.7 | length 361.2
  Top Layer w10: U14.7@4522.99,1403.86 4522.99,1226.5 C101.1@4562.5,1187
  Top Layer w30: C101.1@4562.5,1187 4605.96,1143.54 C100.1@4605.96,1077
NetC102_1: C102.1 R101.2 U14.27 | length 318.6
  Top Layer w10: U14.27@4621.42,1636.14 4621.42,1734.41 C102.1@4727.01,1840
  Top Layer w20: R101.2@4722.5,1909.18 4722.5,1844.5 C102.1@4727.01,1840
NetC102_2: C102.2 R102.2 U14.26 | length 367.8
  Top Layer w10: U14.26@4641.1,1636.14 4641.1,1721.1 4720,1800 4774.7,1800 4790,1815.3 C102.2@4790,1840
  Top Layer w20: C102.2@4790,1840 4792.5,1842.5 R102.2@4792.5,1909.18
NetC103_1: C103.1 R103.2 U14.12 | length 310.2
  Top Layer w10: U14.12@4621.42,1403.86 4621.42,1340.43 4622.56,1339.29 4622.56,1282.32 4621.42,1281.19 4621.42,1279.38 4621.42,1269.41 C103.1@4688.5,1202.32
  Top Layer w20: R103.2@4680,1125.94 4680,1193.82 C103.1@4688.5,1202.32
NetC103_2: C103.2 R104.2 U14.13 | length 358.6
  Top Layer w10: U14.13@4641.1,1403.86 4641.1,1288.9 4690,1240 4743.59,1240 4751.5,1232.09 C103.2@4751.5,1202.32
  Top Layer w20: C103.2@4751.5,1202.32 4760,1193.82 R104.2@4760,1125.94
NetC104_1: C104.1 R105.2 U14.14 | length 426.1
  Top Layer w10: U14.14@4660.79,1403.86 4660.79,1294.49 4692.64,1262.64 4817.36,1262.64 4836.71,1243.29 C104.1@4836.71,1203.62
  Top Layer w20: R105.2@4828.21,1127.24 4828.21,1195.12 C104.1@4836.71,1203.62
NetC104_2: C104.2 R106.2 U14.15 | length 444.2
  Top Layer w10: U14.15@4680.47,1403.86 4680.47,1309.53 4709.44,1280.56 4839.44,1280.56 4899.7,1220.3 C104.2@4899.7,1203.62
  Top Layer w20: R106.2@4898.21,1127.24 4898.21,1202.13 C104.2@4899.7,1203.62
NetC105_2: C105.2 R108.2 U13.3 | length 195.7
  Top Layer w10: C105.2@5530,1741.5 5530,1750 5586.46,1806.46 U13.3@5586.46,1843.86
  Top Layer w20: R108.2@5460,1741.5 C105.2@5530,1741.5
NetC106_2: C106.2 R110.2 U12.3 | length 200.5
  Top Layer w10: C106.2@5520.73,915.94 5520.73,930.73 5575.14,985.14 U12.3@5575.14,1023.86
  Top Layer w20: R110.2@5450.73,915.94 C106.2@5520.73,915.94
NetC107_2: C107.2 R107.2 R108.1 | length 177.2
  Top Layer w20: C107.2@5380,1808.5 5380,1735.18 R107.2@5382.05,1733.13 5405.37,1733.13 5423.43,1715.08 5423.43,1714.41 5459.33,1678.5 R108.1@5460,1678.5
